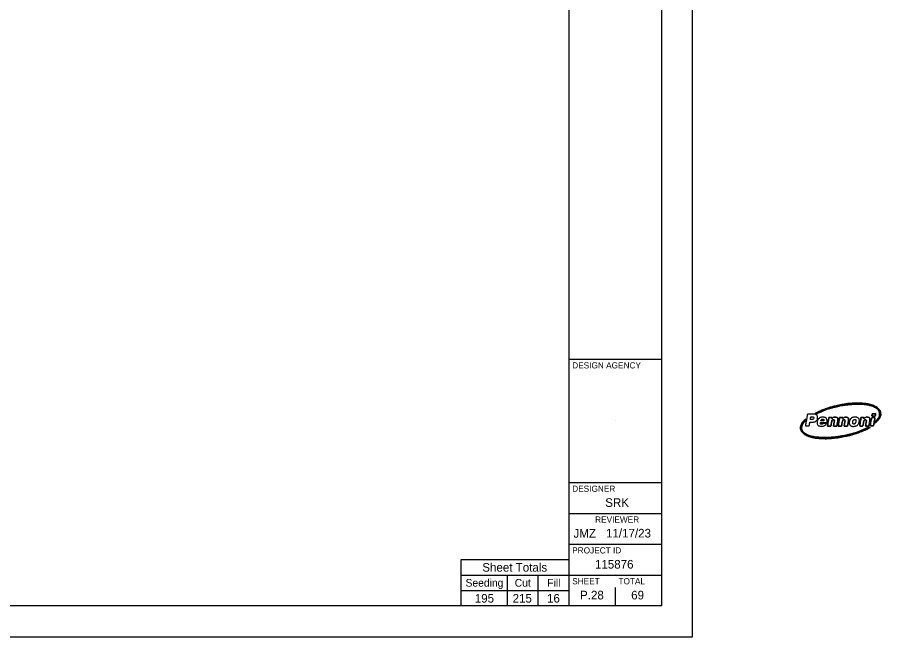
# Model space of a CAD drawing. Extents: x -191 to 37, y -231 to 22.
# Drawn here: x 23.06 to 37.05, y 0 to 10.04 of the extents above; entities that cross this region are included whole.
import ezdxf

# ---------------------------------------------------------------- set-up
doc = ezdxf.new("R2010")
doc.units = 0
for name, color, linetype in [('SH_Border', 7, 'Continuous'), ('SH_Cut_Line', 7, 'Continuous'), ('SH_Data', 7, 'Continuous'), ('SH_Text', 7, 'Continuous')]:
    doc.layers.add(name, color=color, linetype=linetype)

msp = doc.modelspace()

# ---------------------------------------------------------------- linework, layer by layer
at = {"layer": 'SH_Border'}
for p, q in [((32, 0.5), (32, 21.5)), ((32, 4.5), (33.5, 4.5)), ((36.13, 3.503), (36.08, 3.503)), ((32, 2.5), (33.5, 2.5)), ((32, 2), (33.5, 2)), ((32, 1.5), (33.5, 1.5)), ((32, 1), (33.5, 1))]:
    msp.add_line(p, q, dxfattribs=at)
msp.add_lwpolyline([(1.5, 21.5), (33.5, 21.5), (33.5, 0.5), (1.5, 0.5)], close=True, dxfattribs=at)
for points, degree in [([(35.989, 3.621), (35.996, 3.619), (36.002, 3.616), (36.008, 3.615), (36.01, 3.614), (36.013, 3.614), (36.015, 3.615), (36.044, 3.629), (36.072, 3.643), (36.101, 3.655), (36.142, 3.673), (36.185, 3.688), (36.227, 3.701), (36.269, 3.714), (36.312, 3.725), (36.355, 3.734), (36.395, 3.743), (36.435, 3.751), (36.475, 3.756), (36.507, 3.76), (36.539, 3.764), (36.571, 3.767), (36.596, 3.769), (36.622, 3.77), (36.647, 3.771), (36.702, 3.772), (36.757, 3.77), (36.811, 3.762), (36.841, 3.758), (36.87, 3.752), (36.899, 3.742), (36.934, 3.731), (36.968, 3.717), (36.996, 3.691), (37.011, 3.678), (37.023, 3.661), (37.028, 3.641), (37.033, 3.624), (37.034, 3.607), (37.031, 3.589), (37.028, 3.569), (37.018, 3.552), (37.006, 3.536), (36.993, 3.521), (36.979, 3.508), (36.965, 3.495), (36.963, 3.494), (36.962, 3.492), (36.961, 3.49), (36.96, 3.485), (36.959, 3.479), (36.958, 3.473), (36.958, 3.471), (36.957, 3.469), (36.957, 3.465), (36.981, 3.485), (37.003, 3.505), (37.022, 3.529), (37.031, 3.54), (37.039, 3.553), (37.044, 3.566), (37.051, 3.585), (37.051, 3.604), (37.049, 3.623), (37.045, 3.658), (37.029, 3.685), (37.003, 3.708), (36.979, 3.728), (36.951, 3.741), (36.922, 3.752), (36.885, 3.766), (36.847, 3.774), (36.807, 3.779), (36.773, 3.784), (36.737, 3.787), (36.702, 3.788), (36.646, 3.789), (36.589, 3.787), (36.533, 3.781), (36.502, 3.777), (36.472, 3.773), (36.441, 3.768), (36.396, 3.761), (36.351, 3.752), (36.306, 3.74), (36.246, 3.725), (36.187, 3.707), (36.128, 3.684), (36.087, 3.669), (36.047, 3.651), (36.008, 3.631), (36.002, 3.628), (35.996, 3.625), (35.989, 3.621)], 3), ([(35.989, 3.621), (35.996, 3.625), (36.002, 3.628), (36.008, 3.631), (36.047, 3.651), (36.087, 3.669), (36.128, 3.684), (36.187, 3.707), (36.246, 3.725), (36.306, 3.74), (36.351, 3.752), (36.396, 3.761), (36.441, 3.768), (36.472, 3.773), (36.502, 3.777), (36.533, 3.781), (36.589, 3.787), (36.646, 3.789), (36.702, 3.788), (36.737, 3.787), (36.773, 3.784), (36.807, 3.779), (36.847, 3.774), (36.885, 3.766), (36.922, 3.752), (36.951, 3.741), (36.979, 3.728), (37.003, 3.708), (37.029, 3.685), (37.045, 3.658), (37.049, 3.623), (37.051, 3.604), (37.051, 3.585), (37.044, 3.566), (37.039, 3.553), (37.031, 3.54), (37.022, 3.529), (37.003, 3.505), (36.981, 3.485), (36.957, 3.465), (36.957, 3.469), (36.958, 3.471), (36.958, 3.473), (36.959, 3.479), (36.96, 3.485), (36.961, 3.49), (36.962, 3.492), (36.963, 3.494), (36.965, 3.495), (36.979, 3.508), (36.993, 3.521), (37.006, 3.536), (37.018, 3.552), (37.028, 3.569), (37.031, 3.589), (37.034, 3.607), (37.033, 3.624), (37.028, 3.641), (37.023, 3.661), (37.011, 3.678), (36.996, 3.691), (36.968, 3.717), (36.934, 3.731), (36.899, 3.742), (36.87, 3.752), (36.841, 3.758), (36.811, 3.762), (36.757, 3.77), (36.702, 3.772), (36.647, 3.771), (36.622, 3.77), (36.596, 3.769), (36.571, 3.767), (36.539, 3.764), (36.507, 3.76), (36.475, 3.756), (36.435, 3.751), (36.395, 3.743), (36.355, 3.734), (36.312, 3.725), (36.269, 3.714), (36.227, 3.701), (36.185, 3.688), (36.142, 3.673), (36.101, 3.655), (36.072, 3.643), (36.044, 3.629), (36.015, 3.615), (36.013, 3.614), (36.01, 3.614), (36.008, 3.615), (36.002, 3.616), (35.996, 3.619), (35.989, 3.621)], 3), ([(36.877, 3.392), (36.877, 3.392), (36.877, 3.393), (36.877, 3.393), (36.867, 3.393), (36.857, 3.393), (36.847, 3.393), (36.845, 3.393), (36.842, 3.392), (36.84, 3.391), (36.802, 3.372), (36.764, 3.355), (36.725, 3.34), (36.667, 3.317), (36.608, 3.298), (36.548, 3.283), (36.505, 3.271), (36.462, 3.262), (36.418, 3.254), (36.393, 3.25), (36.368, 3.246), (36.343, 3.242), (36.318, 3.239), (36.292, 3.236), (36.266, 3.234), (36.242, 3.232), (36.218, 3.23), (36.194, 3.23), (36.166, 3.229), (36.138, 3.228), (36.109, 3.229), (36.078, 3.231), (36.047, 3.233), (36.017, 3.236), (35.979, 3.24), (35.941, 3.248), (35.904, 3.259), (35.873, 3.269), (35.843, 3.282), (35.816, 3.302), (35.799, 3.314), (35.785, 3.329), (35.776, 3.348), (35.764, 3.374), (35.765, 3.4), (35.776, 3.427), (35.785, 3.45), (35.799, 3.47), (35.816, 3.488), (35.821, 3.494), (35.827, 3.5), (35.827, 3.509), (35.827, 3.514), (35.829, 3.52), (35.83, 3.526), (35.829, 3.525), (35.828, 3.525), (35.827, 3.524), (35.818, 3.514), (35.808, 3.505), (35.799, 3.494), (35.779, 3.472), (35.763, 3.448), (35.755, 3.419), (35.75, 3.402), (35.749, 3.385), (35.752, 3.368), (35.757, 3.341), (35.771, 3.319), (35.791, 3.301), (35.814, 3.28), (35.841, 3.266), (35.869, 3.254), (35.916, 3.235), (35.965, 3.225), (36.016, 3.219), (36.046, 3.216), (36.077, 3.214), (36.108, 3.212), (36.151, 3.211), (36.193, 3.211), (36.235, 3.215), (36.27, 3.217), (36.304, 3.221), (36.338, 3.225), (36.369, 3.229), (36.399, 3.234), (36.43, 3.239), (36.484, 3.249), (36.538, 3.261), (36.591, 3.276), (36.636, 3.289), (36.681, 3.304), (36.724, 3.321), (36.768, 3.338), (36.81, 3.356), (36.851, 3.377), (36.86, 3.382), (36.868, 3.387), (36.877, 3.392)], 3), ([(36.877, 3.392), (36.868, 3.387), (36.86, 3.382), (36.851, 3.377), (36.81, 3.356), (36.768, 3.338), (36.724, 3.321), (36.681, 3.304), (36.636, 3.289), (36.591, 3.276), (36.538, 3.261), (36.484, 3.249), (36.43, 3.239), (36.399, 3.234), (36.369, 3.229), (36.338, 3.225), (36.304, 3.221), (36.27, 3.217), (36.235, 3.215), (36.193, 3.211), (36.151, 3.211), (36.108, 3.212), (36.077, 3.214), (36.046, 3.216), (36.016, 3.219), (35.965, 3.225), (35.916, 3.235), (35.869, 3.254), (35.841, 3.266), (35.814, 3.28), (35.791, 3.301), (35.771, 3.319), (35.757, 3.341), (35.752, 3.368), (35.749, 3.385), (35.75, 3.402), (35.755, 3.419), (35.763, 3.448), (35.779, 3.472), (35.799, 3.494), (35.808, 3.505), (35.818, 3.514), (35.827, 3.524), (35.828, 3.525), (35.829, 3.525), (35.83, 3.526), (35.829, 3.52), (35.827, 3.514), (35.827, 3.509), (35.827, 3.5), (35.821, 3.494), (35.816, 3.488), (35.799, 3.47), (35.785, 3.45), (35.776, 3.427), (35.765, 3.4), (35.764, 3.374), (35.776, 3.348), (35.785, 3.329), (35.799, 3.314), (35.816, 3.302), (35.843, 3.282), (35.873, 3.269), (35.904, 3.259), (35.941, 3.248), (35.979, 3.24), (36.017, 3.236), (36.047, 3.233), (36.078, 3.231), (36.109, 3.229), (36.138, 3.228), (36.166, 3.229), (36.194, 3.23), (36.218, 3.23), (36.242, 3.232), (36.266, 3.234), (36.292, 3.236), (36.318, 3.239), (36.343, 3.242), (36.368, 3.246), (36.393, 3.25), (36.418, 3.254), (36.462, 3.262), (36.505, 3.271), (36.548, 3.283), (36.608, 3.298), (36.667, 3.317), (36.725, 3.34), (36.764, 3.355), (36.802, 3.372), (36.84, 3.391), (36.842, 3.392), (36.845, 3.393), (36.847, 3.393), (36.857, 3.393), (36.867, 3.393), (36.877, 3.393), (36.877, 3.393), (36.877, 3.392), (36.877, 3.392)], 3), ([(36, 3.602), (35.988, 3.608), (35.974, 3.61), (35.961, 3.61), (35.929, 3.611), (35.897, 3.61), (35.866, 3.61), (35.863, 3.61), (35.862, 3.61), (35.862, 3.608), (35.858, 3.586), (35.855, 3.565), (35.851, 3.543), (35.845, 3.509), (35.839, 3.474), (35.833, 3.439), (35.831, 3.432), (35.83, 3.424), (35.829, 3.417)], 3), ([(35.902, 3.477), (35.91, 3.477), (35.917, 3.477), (35.924, 3.477), (35.937, 3.477), (35.949, 3.477), (35.962, 3.48), (35.979, 3.483), (35.994, 3.49), (36.006, 3.502), (36.021, 3.518), (36.027, 3.537), (36.027, 3.559), (36.028, 3.578), (36.019, 3.593), (36, 3.602)], 3), ([(35.91, 3.522), (35.912, 3.536), (35.915, 3.55), (35.917, 3.563), (35.917, 3.564), (35.919, 3.565), (35.919, 3.565), (35.931, 3.565), (35.942, 3.567), (35.954, 3.563), (35.964, 3.56), (35.968, 3.554), (35.966, 3.543)], 3), ([(35.966, 3.543), (35.963, 3.531), (35.955, 3.523), (35.942, 3.522), (35.932, 3.522), (35.921, 3.522), (35.91, 3.522)], 3), ([(36.182, 3.508), (36.178, 3.533), (36.165, 3.55), (36.141, 3.557), (36.128, 3.562), (36.114, 3.562), (36.101, 3.561), (36.079, 3.558), (36.06, 3.549), (36.044, 3.532), (36.03, 3.517), (36.022, 3.5), (36.02, 3.479), (36.017, 3.45), (36.029, 3.426), (36.058, 3.417), (36.074, 3.412), (36.09, 3.411), (36.107, 3.414), (36.124, 3.416), (36.141, 3.422), (36.155, 3.434), (36.162, 3.441), (36.169, 3.449), (36.173, 3.459)], 3), ([(36.08, 3.503), (36.081, 3.515), (36.09, 3.525), (36.103, 3.527), (36.109, 3.528), (36.115, 3.528), (36.12, 3.525), (36.128, 3.521), (36.131, 3.513), (36.13, 3.503)], 3), ([(36.181, 3.475), (36.183, 3.486), (36.184, 3.497), (36.182, 3.508)], 2), ([(36.188, 3.416), (36.188, 3.415), (36.189, 3.415), (36.189, 3.415), (36.206, 3.415), (36.223, 3.415), (36.24, 3.415), (36.243, 3.415), (36.243, 3.416), (36.244, 3.418), (36.245, 3.426), (36.246, 3.435), (36.248, 3.443), (36.251, 3.46), (36.254, 3.478), (36.258, 3.495), (36.26, 3.505), (36.264, 3.513), (36.274, 3.515), (36.287, 3.519), (36.301, 3.516), (36.299, 3.497), (36.297, 3.482), (36.294, 3.468), (36.292, 3.454), (36.29, 3.441), (36.287, 3.428), (36.285, 3.416), (36.286, 3.415), (36.286, 3.415), (36.287, 3.415), (36.304, 3.415), (36.321, 3.415), (36.338, 3.415), (36.34, 3.415), (36.341, 3.416), (36.341, 3.419), (36.345, 3.442), (36.349, 3.466), (36.354, 3.49), (36.356, 3.502), (36.358, 3.515), (36.356, 3.527), (36.354, 3.543), (36.345, 3.554), (36.329, 3.558), (36.307, 3.564), (36.288, 3.56), (36.271, 3.545), (36.267, 3.542), (36.263, 3.538), (36.259, 3.535), (36.26, 3.542), (36.262, 3.549), (36.263, 3.557), (36.247, 3.557), (36.23, 3.557), (36.214, 3.556), (36.213, 3.556), (36.212, 3.555), (36.212, 3.554), (36.211, 3.55), (36.21, 3.545), (36.209, 3.541), (36.204, 3.511), (36.199, 3.48), (36.193, 3.45), (36.191, 3.438), (36.19, 3.427), (36.188, 3.416)], 3), ([(36.188, 3.416), (36.19, 3.427), (36.191, 3.438), (36.193, 3.45), (36.199, 3.48), (36.204, 3.511), (36.209, 3.541), (36.21, 3.545), (36.211, 3.55), (36.212, 3.554), (36.212, 3.555), (36.213, 3.556), (36.214, 3.556), (36.23, 3.557), (36.247, 3.557), (36.263, 3.557), (36.262, 3.549), (36.26, 3.542), (36.259, 3.535), (36.263, 3.538), (36.267, 3.542), (36.271, 3.545), (36.288, 3.56), (36.307, 3.564), (36.329, 3.558), (36.345, 3.554), (36.354, 3.543), (36.356, 3.527), (36.358, 3.515), (36.356, 3.502), (36.354, 3.49), (36.349, 3.466), (36.345, 3.442), (36.341, 3.419), (36.341, 3.416), (36.34, 3.415), (36.338, 3.415), (36.321, 3.415), (36.304, 3.415), (36.287, 3.415), (36.286, 3.415), (36.286, 3.415), (36.285, 3.416), (36.287, 3.428), (36.29, 3.441), (36.292, 3.454), (36.294, 3.468), (36.297, 3.482), (36.299, 3.497), (36.301, 3.516), (36.287, 3.519), (36.274, 3.515), (36.264, 3.513), (36.26, 3.505), (36.258, 3.495), (36.254, 3.478), (36.251, 3.46), (36.248, 3.443), (36.246, 3.435), (36.245, 3.426), (36.244, 3.418), (36.243, 3.416), (36.243, 3.415), (36.24, 3.415), (36.223, 3.415), (36.206, 3.415), (36.189, 3.415), (36.189, 3.415), (36.188, 3.415), (36.188, 3.416)], 3), ([(36.361, 3.416), (36.361, 3.415), (36.361, 3.415), (36.361, 3.415), (36.379, 3.415), (36.396, 3.415), (36.414, 3.415), (36.415, 3.415), (36.416, 3.417), (36.416, 3.418), (36.42, 3.435), (36.422, 3.452), (36.426, 3.469), (36.427, 3.479), (36.429, 3.49), (36.432, 3.5), (36.436, 3.513), (36.448, 3.519), (36.461, 3.516), (36.467, 3.515), (36.47, 3.511), (36.471, 3.505), (36.472, 3.502), (36.472, 3.499), (36.472, 3.496), (36.47, 3.485), (36.468, 3.473), (36.466, 3.462), (36.463, 3.447), (36.461, 3.431), (36.458, 3.416), (36.458, 3.415), (36.459, 3.415), (36.459, 3.415), (36.476, 3.415), (36.494, 3.415), (36.511, 3.415), (36.512, 3.415), (36.514, 3.417), (36.514, 3.418), (36.518, 3.441), (36.522, 3.463), (36.526, 3.485), (36.528, 3.497), (36.53, 3.509), (36.53, 3.522), (36.53, 3.537), (36.524, 3.55), (36.508, 3.556), (36.488, 3.564), (36.468, 3.562), (36.45, 3.55), (36.444, 3.545), (36.438, 3.54), (36.432, 3.535), (36.434, 3.543), (36.435, 3.549), (36.436, 3.557), (36.419, 3.557), (36.404, 3.557), (36.388, 3.557), (36.385, 3.557), (36.385, 3.555), (36.385, 3.553), (36.38, 3.529), (36.376, 3.505), (36.372, 3.481), (36.368, 3.46), (36.364, 3.438), (36.361, 3.416)], 3), ([(36.361, 3.416), (36.364, 3.438), (36.368, 3.46), (36.372, 3.481), (36.376, 3.505), (36.38, 3.529), (36.385, 3.553), (36.385, 3.555), (36.385, 3.557), (36.388, 3.557), (36.404, 3.557), (36.419, 3.557), (36.436, 3.557), (36.435, 3.549), (36.434, 3.543), (36.432, 3.535), (36.438, 3.54), (36.444, 3.545), (36.45, 3.55), (36.468, 3.562), (36.488, 3.564), (36.508, 3.556), (36.524, 3.55), (36.53, 3.537), (36.53, 3.522), (36.53, 3.509), (36.528, 3.497), (36.526, 3.485), (36.522, 3.463), (36.518, 3.441), (36.514, 3.418), (36.514, 3.417), (36.512, 3.415), (36.511, 3.415), (36.494, 3.415), (36.476, 3.415), (36.459, 3.415), (36.459, 3.415), (36.458, 3.415), (36.458, 3.416), (36.461, 3.431), (36.463, 3.447), (36.466, 3.462), (36.468, 3.473), (36.47, 3.485), (36.472, 3.496), (36.472, 3.499), (36.472, 3.502), (36.471, 3.505), (36.47, 3.511), (36.467, 3.515), (36.461, 3.516), (36.448, 3.519), (36.436, 3.513), (36.432, 3.5), (36.429, 3.49), (36.427, 3.479), (36.426, 3.469), (36.422, 3.452), (36.42, 3.435), (36.416, 3.418), (36.416, 3.417), (36.415, 3.415), (36.414, 3.415), (36.396, 3.415), (36.379, 3.415), (36.361, 3.415), (36.361, 3.415), (36.361, 3.415), (36.361, 3.416)], 3), ([(36.704, 3.508), (36.702, 3.53), (36.691, 3.545), (36.671, 3.554), (36.652, 3.562), (36.632, 3.562), (36.612, 3.558), (36.588, 3.553), (36.568, 3.541), (36.555, 3.52), (36.554, 3.518), (36.553, 3.515), (36.552, 3.513), (36.551, 3.511), (36.55, 3.509), (36.549, 3.507), (36.544, 3.496), (36.541, 3.484), (36.541, 3.472), (36.541, 3.47), (36.541, 3.467), (36.541, 3.465), (36.541, 3.457), (36.543, 3.45), (36.546, 3.444), (36.546, 3.443), (36.547, 3.441), (36.547, 3.44), (36.548, 3.439), (36.548, 3.438), (36.549, 3.437), (36.551, 3.434), (36.554, 3.43), (36.558, 3.427), (36.559, 3.426), (36.562, 3.424), (36.564, 3.423), (36.564, 3.422), (36.565, 3.422), (36.565, 3.422), (36.567, 3.421), (36.568, 3.42), (36.569, 3.42), (36.571, 3.419), (36.573, 3.418), (36.575, 3.417), (36.586, 3.412), (36.597, 3.411), (36.609, 3.41)], 3), ([(36.597, 3.471), (36.597, 3.487), (36.6, 3.501), (36.609, 3.513), (36.614, 3.519), (36.621, 3.523), (36.629, 3.523), (36.638, 3.523), (36.644, 3.52), (36.646, 3.511), (36.647, 3.505), (36.648, 3.498), (36.647, 3.491)], 3), ([(36.609, 3.41), (36.617, 3.411), (36.624, 3.412), (36.631, 3.413), (36.65, 3.416), (36.667, 3.425), (36.68, 3.439), (36.697, 3.459), (36.705, 3.482), (36.704, 3.508)], 3), ([(36.731, 3.556), (36.723, 3.509), (36.715, 3.462), (36.707, 3.415), (36.726, 3.415), (36.744, 3.415), (36.762, 3.415), (36.765, 3.43), (36.767, 3.444), (36.77, 3.458), (36.772, 3.471), (36.774, 3.484), (36.777, 3.496), (36.78, 3.51), (36.79, 3.517), (36.803, 3.517), (36.812, 3.516), (36.817, 3.511), (36.818, 3.503), (36.818, 3.5), (36.818, 3.497), (36.818, 3.494), (36.814, 3.475), (36.811, 3.456), (36.808, 3.437), (36.807, 3.43), (36.805, 3.423), (36.804, 3.415), (36.823, 3.415), (36.841, 3.415), (36.859, 3.415), (36.86, 3.417), (36.86, 3.418), (36.86, 3.419), (36.864, 3.44), (36.868, 3.462), (36.871, 3.483), (36.874, 3.497), (36.877, 3.51), (36.876, 3.525), (36.875, 3.541), (36.866, 3.553), (36.85, 3.558), (36.825, 3.565), (36.803, 3.559), (36.785, 3.541), (36.783, 3.539), (36.781, 3.537), (36.779, 3.535), (36.779, 3.535), (36.779, 3.535), (36.778, 3.536), (36.78, 3.542), (36.781, 3.549), (36.782, 3.556), (36.765, 3.556), (36.748, 3.556), (36.731, 3.556)], 3), ([(36.731, 3.556), (36.748, 3.556), (36.765, 3.556), (36.782, 3.556), (36.781, 3.549), (36.78, 3.542), (36.778, 3.536), (36.779, 3.535), (36.779, 3.535), (36.779, 3.535), (36.781, 3.537), (36.783, 3.539), (36.785, 3.541), (36.803, 3.559), (36.825, 3.565), (36.85, 3.558), (36.866, 3.553), (36.875, 3.541), (36.876, 3.525), (36.877, 3.51), (36.874, 3.497), (36.871, 3.483), (36.868, 3.462), (36.864, 3.44), (36.86, 3.419), (36.86, 3.418), (36.86, 3.417), (36.859, 3.415), (36.841, 3.415), (36.823, 3.415), (36.804, 3.415), (36.805, 3.423), (36.807, 3.43), (36.808, 3.437), (36.811, 3.456), (36.814, 3.475), (36.818, 3.494), (36.818, 3.497), (36.818, 3.5), (36.818, 3.503), (36.817, 3.511), (36.812, 3.516), (36.803, 3.517), (36.79, 3.517), (36.78, 3.51), (36.777, 3.496), (36.774, 3.484), (36.772, 3.471), (36.77, 3.458), (36.767, 3.444), (36.765, 3.43), (36.762, 3.415), (36.744, 3.415), (36.726, 3.415), (36.707, 3.415), (36.715, 3.462), (36.723, 3.509), (36.731, 3.556)], 3), ([(36.934, 3.417), (36.916, 3.417), (36.898, 3.417), (36.879, 3.417), (36.887, 3.464), (36.895, 3.51), (36.903, 3.557), (36.922, 3.557), (36.94, 3.557), (36.959, 3.557), (36.95, 3.51), (36.942, 3.464), (36.934, 3.417)], 3), ([(36.934, 3.417), (36.942, 3.464), (36.95, 3.51), (36.959, 3.557), (36.94, 3.557), (36.922, 3.557), (36.903, 3.557), (36.895, 3.51), (36.887, 3.464), (36.879, 3.417), (36.898, 3.417), (36.916, 3.417), (36.934, 3.417)], 3), ([(36.969, 3.615), (36.967, 3.603), (36.965, 3.591), (36.962, 3.578), (36.962, 3.577), (36.96, 3.576), (36.959, 3.576), (36.942, 3.576), (36.925, 3.576), (36.907, 3.576), (36.908, 3.586), (36.91, 3.595), (36.912, 3.604), (36.912, 3.606), (36.913, 3.609), (36.913, 3.611), (36.913, 3.615), (36.914, 3.616), (36.918, 3.615), (36.933, 3.615), (36.949, 3.615), (36.964, 3.615), (36.966, 3.615), (36.967, 3.615), (36.969, 3.615)], 3), ([(36.969, 3.615), (36.967, 3.615), (36.966, 3.615), (36.964, 3.615), (36.949, 3.615), (36.933, 3.615), (36.918, 3.615), (36.914, 3.616), (36.913, 3.615), (36.913, 3.611), (36.913, 3.609), (36.912, 3.606), (36.912, 3.604), (36.91, 3.595), (36.908, 3.586), (36.907, 3.576), (36.925, 3.576), (36.942, 3.576), (36.959, 3.576), (36.96, 3.576), (36.962, 3.577), (36.962, 3.578), (36.965, 3.591), (36.967, 3.603), (36.969, 3.615)], 3), ([(35.829, 3.417), (35.83, 3.417), (35.83, 3.417), (35.831, 3.417), (35.85, 3.417), (35.87, 3.417), (35.889, 3.417), (35.892, 3.417), (35.892, 3.418), (35.892, 3.42), (35.894, 3.431), (35.896, 3.442), (35.898, 3.454), (35.899, 3.461), (35.901, 3.469), (35.902, 3.477)], 3), ([(36.173, 3.459), (36.156, 3.459), (36.139, 3.459), (36.122, 3.458), (36.121, 3.458), (36.12, 3.457), (36.119, 3.457), (36.115, 3.454), (36.111, 3.45), (36.106, 3.448), (36.09, 3.442), (36.073, 3.451), (36.074, 3.47), (36.074, 3.474), (36.075, 3.475), (36.079, 3.475), (36.111, 3.475), (36.143, 3.475), (36.175, 3.475), (36.177, 3.475), (36.179, 3.475), (36.181, 3.475)], 3), ([(36.647, 3.491), (36.647, 3.481), (36.644, 3.471), (36.639, 3.462), (36.633, 3.452), (36.623, 3.447), (36.612, 3.449), (36.606, 3.45), (36.601, 3.453), (36.599, 3.459), (36.598, 3.464), (36.597, 3.469), (36.597, 3.471)], 3)]:
    msp.add_open_spline(points, degree=degree, dxfattribs=at)
at = {"layer": 'SH_Cut_Line'}
msp.add_lwpolyline([(0, 0), (34, 0), (34, 22), (0, 22)], close=True, dxfattribs=at)
at = {"layer": 'SH_Data'}
for p, q in [((32.75, 3.5), (32.75, 3.5)), ((30.25, 0.5), (30.25, 1.25)), ((30.25, 1.25), (32, 1.25)), ((30.25, 1), (32, 1)), ((31, 0.5), (31, 1)), ((31.5, 0.5), (31.5, 1)), ((30.25, 0.75), (32, 0.75)), ((32.75, 0.5), (32.75, 0.8)), ((30.632, 0.625), (30.632, 0.625)), ((31.254, 0.625), (31.254, 0.625)), ((31.76, 0.625), (31.76, 0.625)), ((32.375, 0.675), (32.375, 0.675))]:
    msp.add_line(p, q, dxfattribs=at)

# ---------------------------------------------------------------- texts
for s, height, p in [('DESIGN AGENCY', 0.1, (32.05, 4.35)), ('DESIGNER', 0.1, (32.05, 2.35)), ('SRK', 0.14, (32.585, 2.105)), ('REVIEWER', 0.1, (32.422, 1.85)), ('JMZ', 0.14, (32.071, 1.605)), ('11/17/23', 0.14, (32.598, 1.609)), ('PROJECT ID', 0.1, (32.05, 1.35)), ('Sheet Totals', 0.14, (30.593, 1.055)), ('115876', 0.14, (32.419, 1.105)), ('Seeding', 0.125, (30.321, 0.812)), ('Cut', 0.125, (31.118, 0.812)), ('Fill', 0.125, (31.646, 0.812)), ('SHEET', 0.1, (32.05, 0.85)), ('TOTAL', 0.1, (32.8, 0.85)), ('P.28', 0.14, (32.177, 0.605)), ('69', 0.14, (33.006, 0.605))]:
    msp.add_text(s, height=height, dxfattribs=at).set_placement(p)
at = {"layer": 'SH_Text'}
for s, p in [('195', (30.471, 0.553)), ('215', (31.084, 0.553)), ('16', (31.642, 0.553))]:
    msp.add_text(s, height=0.14, dxfattribs=at).set_placement(p)

doc.saveas('drawing.dxf')
